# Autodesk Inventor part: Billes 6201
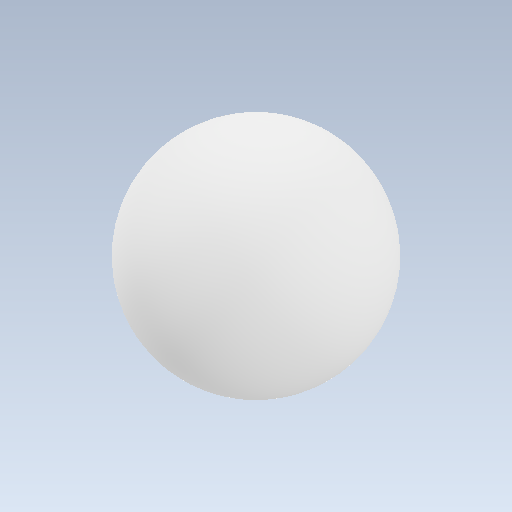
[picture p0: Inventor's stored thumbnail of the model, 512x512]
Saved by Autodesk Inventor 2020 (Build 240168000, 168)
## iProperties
Created: 2003-07
Part Number: Billes 6201
Material: Générique
Document SubType Name: Modeling
Designer: Bruno
Density: 1 g/cm^3
Appearance: Par défaut
Author: Bruno
Sending System: SolidWorks 2001 Plus
Last Author: Faugeron
Last Saved: 2003-08-12
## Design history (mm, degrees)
feature "Base1"
node "Solide1"
